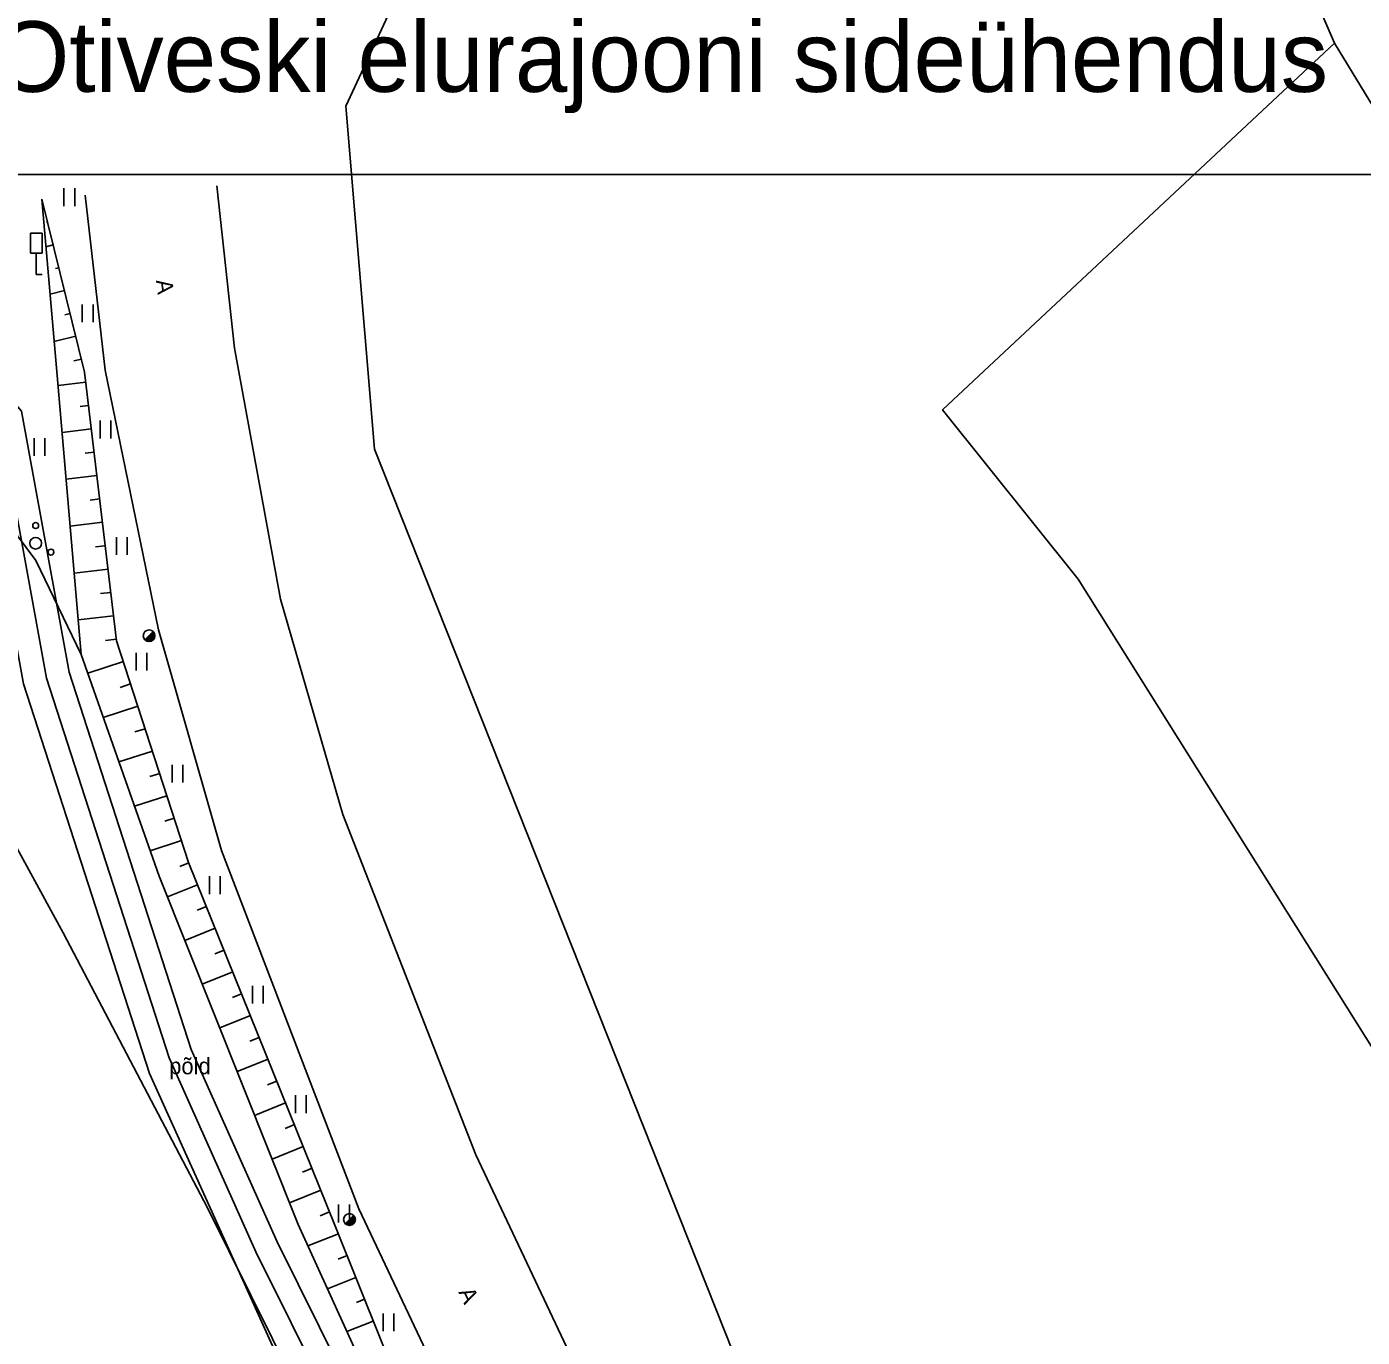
# Model space of a CAD drawing. Extents: x 554947 to 555436, y 6564938 to 6565792.
# Drawn here: x 555060.6 to 555117.3, y 6565555.5 to 6565611.2 of the extents above; entities that cross this region are included whole.
import ezdxf

# ---------------------------------------------------------------- set-up
doc = ezdxf.new("R2010")
doc.units = 0
for name, color, linetype in [('HALJASTUS', 7, 'Continuous'), ('KASUTUSALA', 7, 'Continuous'), ('KPKAABEL', 7, 'Continuous'), ('LIIKLUS', 7, 'Continuous'), ('PIIR', 7, 'Continuous'), ('POST', 7, 'Continuous'), ('PR_SIDE', 7, 'Continuous'), ('PUU', 7, 'Continuous'), ('RELJEEF', 7, 'Continuous'), ('TEE', 7, 'Continuous'), ('VORMISTUS_2', 7, 'Continuous')]:
    doc.layers.add(name, color=color, linetype=linetype)

msp = doc.modelspace()

# ---------------------------------------------------------------- linework, layer by layer
at = {"layer": 'HALJASTUS'}
for p, q in [((555062.138, 6565604.331), (555062.138, 6565603.57)), ((555062.593, 6565604.331), (555062.593, 6565603.57)), ((555062.918, 6565599.392), (555062.918, 6565598.631)), ((555063.373, 6565599.392), (555063.373, 6565598.631)), ((555063.674, 6565594.45), (555063.674, 6565593.689)), ((555064.129, 6565594.45), (555064.129, 6565593.689)), ((555060.874, 6565593.707), (555060.874, 6565592.946)), ((555061.329, 6565593.707), (555061.329, 6565592.946)), ((555064.365, 6565589.498), (555064.365, 6565588.737)), ((555064.82, 6565589.498), (555064.82, 6565588.737)), ((555065.207, 6565584.581), (555065.207, 6565583.82)), ((555065.662, 6565584.581), (555065.662, 6565583.82)), ((555066.741, 6565579.822), (555066.741, 6565579.061)), ((555067.196, 6565579.822), (555067.196, 6565579.061)), ((555068.321, 6565575.079), (555068.321, 6565574.318)), ((555068.776, 6565575.079), (555068.776, 6565574.318)), ((555070.154, 6565570.427), (555070.154, 6565569.666)), ((555070.609, 6565570.427), (555070.609, 6565569.666)), ((555071.986, 6565565.775), (555071.986, 6565565.014)), ((555072.441, 6565565.775), (555072.441, 6565565.014)), ((555073.818, 6565561.123), (555073.818, 6565560.362)), ((555074.273, 6565561.123), (555074.273, 6565560.362)), ((555075.712, 6565556.497), (555075.712, 6565555.735)), ((555076.167, 6565556.497), (555076.167, 6565555.735))]:
    msp.add_line(p, q, dxfattribs=at)
msp.add_lwpolyline([(555033.078, 6565606.955), (555042.182, 6565603.884), (555055.024, 6565596.272), (555056.694, 6565594.201), (555060.942, 6565588.507), (555062.867, 6565584.513)], dxfattribs=at)
at = {"layer": 'KASUTUSALA'}
msp.add_lwpolyline([(555144.16, 6565410.6), (555124.27, 6565454.45), (555113.82, 6565475.68), (555076.76, 6565542.38), (555065.78, 6565566.7), (555060.42, 6565583.26), (555057.954, 6565596.723), (555059.656, 6565595.654), (555060.33, 6565594.851), (555062.363, 6565583.75), (555067.552, 6565567.72), (555071.198, 6565559.537), (555075.701, 6565550.483), (555082.19, 6565538.355), (555091.441, 6565521.624), (555102.427, 6565501.094), (555109.9, 6565486.829), (555116.169, 6565475.57), (555126.773, 6565453.774), (555135.197, 6565435.201)], dxfattribs=at)
at = {"layer": 'KPKAABEL'}
msp.add_lwpolyline([(555022.085, 6565654.913), (555021.622, 6565652.627), (555021.526, 6565649.765), (555022.786, 6565647.231), (555026.485, 6565641.465), (555030.606, 6565629.728), (555035.378, 6565618.813), (555040.844, 6565608.057), (555047.089, 6565597.805), (555053.567, 6565587.292), (555056.073, 6565583.696), (555062.108, 6565572.667), (555068.248, 6565560.982), (555073.771, 6565549.852), (555080.106, 6565537.978), (555085.958, 6565527.605), (555092.403, 6565515.607), (555098.402, 6565504.536), (555104.641, 6565492.438), (555110.839, 6565480.82), (555116.697, 6565469.072), (555121.821, 6565458.116), (555126.894, 6565446.731), (555132.737, 6565435.388)], dxfattribs=at)
at = {"layer": 'LIIKLUS'}
for p, q in [((555060.71, 6565602.417), (555060.71, 6565601.567)), ((555061.21, 6565602.417), (555060.71, 6565602.417)), ((555061.21, 6565602.417), (555061.21, 6565601.567)), ((555061.21, 6565601.567), (555060.71, 6565601.567)), ((555060.96, 6565601.567), (555060.96, 6565600.667)), ((555061.21, 6565600.667), (555060.96, 6565600.667))]:
    msp.add_line(p, q, dxfattribs=at)
at = {"layer": 'PIIR'}
for points in [[(555016.055, 6565654.913), (555030.24, 6565648.23), (555043.11, 6565640.11), (555053.62, 6565632.14), (555056.61, 6565622.91), (555057.22, 6565600.73), (555060.42, 6565583.26), (555065.78, 6565566.7), (555076.76, 6565542.38), (555113.82, 6565475.68), (554946.63, 6565420.78), (554981.01, 6565316.76), (555160.07, 6565375.54), (555166.64, 6565360.5), (555167.67, 6565357.913)], [(555144.16, 6565410.6), (555124.27, 6565454.45), (555113.82, 6565475.68), (555076.76, 6565542.38), (555065.78, 6565566.7), (555060.42, 6565583.26), (555057.22, 6565600.73), (555056.61, 6565622.91), (555063.43, 6565647.29), (555114.24, 6565634), (555129.77, 6565611.2), (555130.73, 6565621.32), (555138.66, 6565615.26), (555160.12, 6565598.86), (555193.24, 6565604.68), (555193.7, 6565602.7), (555225.47, 6565605.89), (555234.35, 6565605.6), (555251.24, 6565598.48), (555330.71, 6565538.85), (555343.81, 6565536.56), (555350.68, 6565540.44), (555361.56, 6565549.57), (555393.069, 6565582.099)], [(555171.91, 6565394.64), (555091.74, 6565551.94), (555075.34, 6565593.24), (555074.13, 6565607.82), (555079.04, 6565618.4), (555093.56, 6565628.47), (555109.96, 6565624.83), (555116.17, 6565610.5), (555099.5, 6565594.91), (555105.26, 6565587.71), (555119.63, 6565564.84), (555126.35, 6565558.74), (555131.01, 6565550.06), (555139.64, 6565543.1), (555141.68, 6565537.52), (555139.26, 6565529.51), (555139.49, 6565523.98), (555140.65, 6565513.25), (555142.13, 6565499.56), (555141.53, 6565491.02), (555141.65, 6565472.71), (555143.93, 6565463.6), (555153.01, 6565448.47), (555207.22, 6565406.57)], [(555393.069, 6565560.972), (555353.12, 6565523.87), (555343.14, 6565512.46), (555302.6, 6565539.71), (555242.37, 6565583.94), (555179.42, 6565586.32), (555138.98, 6565580.6), (555121.18, 6565602.26), (555116.17, 6565610.5), (555109.96, 6565624.83), (555093.56, 6565628.47), (555079.04, 6565618.4), (555074.13, 6565607.82), (555075.34, 6565593.24), (555091.74, 6565551.94), (555171.91, 6565394.64), (555191.35, 6565341.19), (555195.08, 6565294.61), (555195.28, 6565271.63), (555191.64, 6565237.48)]]:
    msp.add_lwpolyline(points, dxfattribs=at)
msp.add_lwpolyline([(555121.18, 6565602.26), (555138.98, 6565580.6), (555179.42, 6565586.32), (555242.37, 6565583.94), (555302.6, 6565539.71), (555287.77, 6565518.56), (555207.29, 6565506.14), (555200.64, 6565496.23), (555185.97, 6565502.75), (555177.68, 6565506.44), (555171.49, 6565510.85), (555162.05, 6565514.45), (555140.65, 6565513.25), (555139.49, 6565523.98), (555139.26, 6565529.51), (555141.68, 6565537.52), (555139.64, 6565543.1), (555131.01, 6565550.06), (555126.35, 6565558.74), (555119.63, 6565564.84), (555105.26, 6565587.71), (555099.5, 6565594.91), (555116.17, 6565610.5)], close=True, dxfattribs=at)
at = {"layer": 'POST'}
for p, q in [((555065.581, 6565585.125), (555065.934, 6565585.478)), ((555074.1, 6565560.31), (555074.454, 6565560.663))]:
    msp.add_line(p, q, dxfattribs=at)
for centre in [(555065.758, 6565585.302), (555074.278, 6565560.486)]:
    msp.add_circle(centre, 0.25, dxfattribs=at)
for centre, radius, start, end in [((555065.758, 6565585.302), 0.225, 224.8541, 45.0356), ((555065.758, 6565585.302), 0.2, 224.8427, 45.047), ((555065.758, 6565585.302), 0.175, 224.8281, 45.0616), ((555065.758, 6565585.302), 0.15, 224.8087, 45.081), ((555065.758, 6565585.302), 0.125, 224.7814, 45.1083), ((555065.758, 6565585.302), 0.1, 224.7406, 45.1491), ((555065.758, 6565585.302), 0.075, 224.6725, 45.2172), ((555065.758, 6565585.302), 0.05, 224.5363, 45.3534), ((555065.758, 6565585.302), 0.025, 224.1278, 45.7619), ((555074.278, 6565560.486), 0.225, 224.8541, 45.0356), ((555074.278, 6565560.486), 0.2, 224.8427, 45.047), ((555074.278, 6565560.486), 0.175, 224.8281, 45.0616), ((555074.278, 6565560.486), 0.15, 224.8087, 45.081), ((555074.278, 6565560.486), 0.125, 224.7814, 45.1083), ((555074.278, 6565560.486), 0.1, 224.7406, 45.1491), ((555074.278, 6565560.486), 0.075, 224.6725, 45.2172), ((555074.278, 6565560.486), 0.05, 224.5363, 45.3534), ((555074.278, 6565560.486), 0.025, 224.1278, 45.7619)]:
    msp.add_arc(centre, radius, start, end, dxfattribs=at)
at = {"layer": 'PR_SIDE'}
msp.add_lwpolyline([(555074.812, 6565550.025), (555070.293, 6565559.111), (555066.617, 6565567.361), (555061.392, 6565583.505), (555059.394, 6565594.411), (555058.991, 6565594.89), (555051.547, 6565599.57), (555045.662, 6565603.031), (555041.98, 6565609.132), (555036.735, 6565619.454), (555032.194, 6565629.84), (555030.448, 6565634.707), (555030.925, 6565637.158), (555034.991, 6565644.113), (555043.172, 6565658.105), (555043.563, 6565658.774), (555046.326, 6565658.494), (555056.182, 6565651.59), (555064.179, 6565647.804), (555084.437, 6565642.829), (555092.497, 6565648.433), (555092.737, 6565648.737), (555092.881, 6565649.42), (555093.272, 6565650.246)], dxfattribs=at)
at = {"layer": 'PUU'}
for centre, radius in [((555060.934, 6565589.986), 0.125), ((555060.934, 6565589.236), 0.25), ((555061.584, 6565588.861), 0.125)]:
    msp.add_circle(centre, radius, dxfattribs=at)
at = {"layer": 'RELJEEF'}
for p, q in [((555061.435, 6565602.887), (555061.39, 6565602.876)), ((555061.676, 6565601.916), (555061.372, 6565601.841)), ((555061.917, 6565600.946), (555061.78, 6565600.912)), ((555062.158, 6565599.975), (555061.549, 6565599.824)), ((555062.399, 6565599.005), (555062.17, 6565598.948)), ((555062.64, 6565598.034), (555061.725, 6565597.807)), ((555062.88, 6565597.064), (555062.56, 6565596.984)), ((555063.068, 6565596.083), (555061.888, 6565595.943)), ((555063.186, 6565595.09), (555062.823, 6565595.047)), ((555063.304, 6565594.097), (555062.059, 6565593.949)), ((555063.423, 6565593.104), (555063.039, 6565593.059)), ((555063.541, 6565592.111), (555062.229, 6565591.955)), ((555063.659, 6565591.118), (555063.256, 6565591.07)), ((555063.777, 6565590.125), (555062.4, 6565589.962)), ((555063.895, 6565589.132), (555063.472, 6565589.082)), ((555064.013, 6565588.139), (555062.571, 6565587.968)), ((555064.131, 6565587.146), (555063.689, 6565587.094)), ((555064.249, 6565586.153), (555062.742, 6565585.974)), ((555064.367, 6565585.16), (555063.905, 6565585.105)), ((555064.663, 6565584.206), (555063.147, 6565583.714)), ((555064.972, 6565583.255), (555064.524, 6565583.11)), ((555065.281, 6565582.304), (555063.811, 6565581.826)), ((555065.59, 6565581.353), (555065.156, 6565581.212)), ((555065.899, 6565580.402), (555064.474, 6565579.939)), ((555066.209, 6565579.451), (555065.788, 6565579.314)), ((555066.518, 6565578.5), (555065.138, 6565578.052)), ((555066.827, 6565577.549), (555066.42, 6565577.417)), ((555067.136, 6565576.598), (555065.801, 6565576.164)), ((555067.446, 6565575.648), (555067.062, 6565575.492)), ((555067.821, 6565574.72), (555066.534, 6565574.201)), ((555068.195, 6565573.793), (555067.808, 6565573.637)), ((555068.569, 6565572.866), (555067.276, 6565572.344)), ((555068.943, 6565571.938), (555068.555, 6565571.781)), ((555069.318, 6565571.011), (555068.018, 6565570.487)), ((555069.692, 6565570.084), (555069.301, 6565569.926)), ((555070.066, 6565569.156), (555068.761, 6565568.63)), ((555070.44, 6565568.229), (555070.048, 6565568.071)), ((555070.815, 6565567.302), (555069.503, 6565566.772)), ((555071.189, 6565566.374), (555070.794, 6565566.215)), ((555071.563, 6565565.447), (555070.245, 6565564.915)), ((555071.937, 6565564.52), (555071.541, 6565564.36)), ((555072.311, 6565563.592), (555070.988, 6565563.058)), ((555072.686, 6565562.665), (555072.288, 6565562.504)), ((555073.06, 6565561.738), (555071.73, 6565561.201)), ((555073.434, 6565560.81), (555073.034, 6565560.649)), ((555073.807, 6565559.882), (555072.514, 6565559.365)), ((555074.179, 6565558.954), (555073.804, 6565558.804)), ((555074.55, 6565558.026), (555073.343, 6565557.543)), ((555074.922, 6565557.097), (555074.573, 6565556.957)), ((555075.293, 6565556.169), (555074.172, 6565555.72))]:
    msp.add_line(p, q, dxfattribs=at)
for points in [[(555061.195, 6565603.857), (555063.017, 6565596.511), (555064.375, 6565585.09), (555067.439, 6565575.666), (555073.66, 6565560.25), (555078.569, 6565547.982), (555085.069, 6565536.269), (555098.285, 6565513.031), (555109.976, 6565491.648), (555121.815, 6565470.323), (555129.412, 6565453.415), (555139.708, 6565430.653), (555142.38, 6565424.284), (555142.548, 6565422.18)], [(555061.195, 6565603.857), (555061.852, 6565596.368), (555062.867, 6565584.513), (555066.182, 6565575.081), (555072.102, 6565560.271), (555077.804, 6565547.739), (555084.384, 6565535.83), (555097.578, 6565512.389), (555109.285, 6565491.27), (555120.826, 6565469.686), (555128.698, 6565452.867), (555138.479, 6565430.174), (555141.354, 6565423.963), (555142.548, 6565422.18)]]:
    msp.add_lwpolyline(points, dxfattribs=at)
at = {"layer": 'TEE'}
for points in [[(555063.038, 6565604.031), (555063.892, 6565596.591), (555066.154, 6565585.551), (555068.837, 6565576.18), (555074.683, 6565560.943), (555080.389, 6565548.865), (555086.718, 6565537.194), (555099.86, 6565513.945), (555112.002, 6565492.197), (555123.272, 6565470.871), (555131.266, 6565453.894), (555141.635, 6565431.431)], [(555146.697, 6565433.416), (555136.695, 6565455.531), (555128.269, 6565473.276), (555117.193, 6565494.735), (555104.647, 6565516.948), (555091.543, 6565539.738), (555085.215, 6565551.468), (555079.648, 6565563.241), (555074.002, 6565577.71), (555071.343, 6565586.858), (555069.389, 6565597.535), (555068.634, 6565604.431)]]:
    msp.add_lwpolyline(points, dxfattribs=at)
at = {"layer": 'VORMISTUS_2'}
msp.add_lwpolyline([(555186.863, 6565394.913), (555021.863, 6565394.913), (555021.863, 6565604.913), (555186.863, 6565604.913)], close=True, dxfattribs=at)

# ---------------------------------------------------------------- texts
at = {"layer": 'HALJASTUS'}
msp.add_text('põld', height=0.7, rotation=359.9544, dxfattribs=at).set_placement((555066.61, 6565566.661))
at = {"layer": 'TEE'}
for rotation, p in [(277.7014, (555066.045, 6565600.408)), (295.3626, (555078.901, 6565557.402))]:
    msp.add_text('A', height=0.7, rotation=rotation, dxfattribs=at).set_placement(p)
at = {"layer": 'VORMISTUS_2'}
msp.add_text('Kose vald, Tuhala ja Otiveski elurajooni sideühendus', height=3, rotation=360, dxfattribs=at).set_placement((555021.782, 6565608.425))

doc.saveas('drawing.dxf')
